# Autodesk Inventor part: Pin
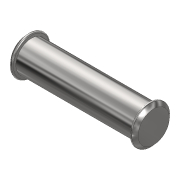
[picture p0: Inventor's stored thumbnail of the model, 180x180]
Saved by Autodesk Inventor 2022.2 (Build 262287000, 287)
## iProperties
Created: 2021-12
Part Number: Pin
Material: ステンレス鋼
Document SubType Name: Modeling
Designer: taeku
Density: 8 g/cm^3
Appearance: 半つや出し
Author: taeku
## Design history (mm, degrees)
sketch "スケッチ1"
  geometry: L1 (0, 8)-(0, 6); L2 (0, 6)-(-45, 6); L3 (-47, 0)-(2, 0); L4 (2, 0)-(2, 6); L5 (-22.5, 6)-(-22.5, 0); L6 (-47, 0)-(-47, 6); L7 (-45, 8)-(-45, 6); A1 r 10 centre (-6, 0) between (2, 6) and (0, 8); A2 r 10 centre (-39, 0) between (-45, 8) and (-47, 6); 1 further point
  constraints: 14 end point, 4 point on circle, 4 symmetric about line, 2 centre point, 2 midpoint, 2 perpendicular, 2 point on line, 1 horizontal, 1 vertical, 1 vertical alignment, 1 other
  dimensions: "d0" = 12 diameter of L2 L3; "d2" = 10 radius of A1; "d3" = 16 diameter of L1.start L3; "d4" = 12 diameter of L4.end L3; "d5" = 45 distance between parallel lines of L7 L1
revolve "回転1" sketch "スケッチ1" stored, may be unused: angle "d6" = 90 deg
fillet "フィレット1" dims "d7" = 0.5
node "ソリッド1"
